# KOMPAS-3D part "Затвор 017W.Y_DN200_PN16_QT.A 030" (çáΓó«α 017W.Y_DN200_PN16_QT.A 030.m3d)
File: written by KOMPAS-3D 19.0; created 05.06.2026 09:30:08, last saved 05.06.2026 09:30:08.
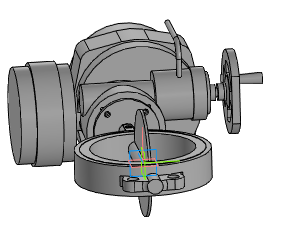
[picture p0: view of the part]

Document properties: Автор: Энергия; Полное имя файла: ..\..\..\3d для проектировщиков\x.x Тип 017W.Y(S) Затвор дисковый поворотный межфланцевый\Затвор 017W.Y(S)_DN32-DN1200_QT.A_MT903.A\Затвор 017W.Y_DN200_PN16_QT.A 030.a3d

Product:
- Part/product: Затвор 017W.Y_DN200_PN16_QT.A 030
    Масса: 126.943

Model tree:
1. Операция без истории:1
